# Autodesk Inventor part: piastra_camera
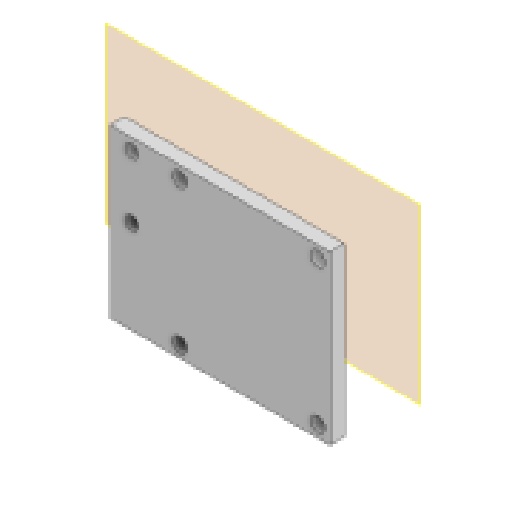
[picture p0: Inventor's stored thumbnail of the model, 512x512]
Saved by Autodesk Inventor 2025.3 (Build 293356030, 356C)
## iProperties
Created: 2026-02
Part Number: piastra_camera
Material: Generico
Document SubType Name: Modeling
Designer: R5800u
Density: 1 g/cm^3
Appearance: Grigio chiaro
Author: R5800u
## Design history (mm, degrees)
node "Piano di lavoro1"
sketch "Schizzo1"
  geometry: L1 (-47, -48.375)-(-13, -48.375) reference; L2 (-13, -48.375)-(-13, -13.375) reference; L3 (-13, -48.375)-(-59, -48.375); L4 (-59, -48.375)-(-59, -13.375); L5 (-59, -13.375)-(-13, -13.375); L6 (-13, -13.375)-(-13, -48.375); L7 (-13, -48.375)-(-11, -48.375); L8 (-11, -48.375)-(-11, -13.375); L9 (-11, -13.375)-(-13, -13.375); L10 (-13, -13.375)-(-13, -48.375); C1 r 1.5 at (-44.5, -45.875) reference; C2 r 1.5 at (-15.5, -45.875) reference; C3 r 1.35 at (-54.5, -15.875) reference; C4 r 1.5 at (-15.5, -15.875) reference; C5 r 1.5 at (-44.5, -15.875) reference; C6 r 1.35 at (-54.5, -28.875) reference; 4 further points
  constraints: 16 end point, 4 parallel, 2 horizontal, 2 perpendicular
  dimensions: "d0" = 46 distance of L4.end L5.end; "d6" = 2 distance of L9.end L8.end
extrude "Estrusione1" new body sketch "Schizzo1" distance "d1" = 3; taper "d2" = 0 deg
sketch "Schizzo2"
  geometry: L1 (40.93, -44.375)-(39.39, -44.375) reference; L2 (41.43, -39.795)-(41.43, -43.875) reference; L3 (18.57, -43.875)-(18.57, -39.795) reference; L4 (20.61, -44.375)-(19.07, -44.375) reference; L5 (19.07, -39.295)-(20.61, -39.295) reference; L6 (36.85, -39.295)-(38.39, -39.295) reference; L7 (41.43, -44.375)-(18.57, -44.375); L8 (18.57, -44.375)-(18.57, -39.295); L9 (18.57, -39.295)-(41.43, -39.295); L10 (41.43, -39.295)-(41.43, -44.375); 13 further points
  constraints: 8 end point, 2 parallel, 1 horizontal, 1 perpendicular
extrude "Estrusione2" cut sketch "Schizzo2" extent not by distance; stored distance "d3" = 0; taper "d4" = 0 deg
fillet "Raccordo1" dims "d5" = 2
node "Solido1"
node "Riferimento1"
node "Riferimento2"
node "Riferimento3"
node "Riferimento4"
node "Riferimento5"
node "Riferimento6"
node "Riferimento7"
node "Riferimento8"
node "Riferimento9"
node "Riferimento10"
node "Riferimento11"
node "Riferimento12"
node "Riferimento13"
node "Riferimento14"
